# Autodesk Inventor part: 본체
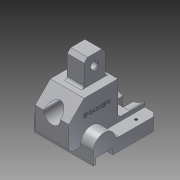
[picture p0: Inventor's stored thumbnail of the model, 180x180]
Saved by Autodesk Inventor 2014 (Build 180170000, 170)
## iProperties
Created: 2016-11
Part Number: 본체
Material: 알루미늄 6061
Document SubType Name: Modeling
Designer: USER
Density: 2.71 g/cm^3
Appearance: 알루미늄 - 평지
Mass: 462.907 g
Surface Area: 317.29 cm^2
Volume: 170.814 cm^3
Author: USER
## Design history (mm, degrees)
sketch "스케치1"
  geometry: L1 (0, 0)-(18, 18); L2 (18, 18)-(58, 18); L3 (58, 18)-(58, -22); L4 (58, -22)-(90, -22); L5 (90, -22)-(90, -42); L6 (90, -42)-(27, -42); L7 (27, -42)-(27, -30); L8 (27, -30)-(0, -30); L9 (0, -30)-(0, 0)
  constraints: 18 end point, 6 perpendicular, 1 horizontal, 1 parallel
  dimensions: "d0" = 45 deg angle of L1 L2; "d1" = 30 distance from line of L8 L1.start; "d2" = 58 distance between parallel lines of L3 L9; "d3" = 90 distance between parallel lines of L5 L9; "d4" = 48 distance between parallel lines of L8 L2; "d5" = 60 distance between parallel lines of L6 L2; "d6" = 20 distance of L4.end L5.end; "d7" = 63 distance of L5.end L6.end
extrude "돌출1" new body sketch "스케치1" stored distance "d8" = 40; taper "d9" = 0 deg
sketch "스케치2"
  geometry: L1 (30, 0)-(30, 27) reference; L2 (30, 27)-(42, 27) reference; L3 (42, 27)-(42, 90) reference; L4 (42, 90)-(22, 90) reference; L5 (-18, 58)-(-18, 18) reference; L6 (27, 14)-(42, 14); L7 (42, 14)-(42, 17); L8 (42, 17)-(35, 17); L9 (35, 17)-(35, 37); L10 (35, 37)-(42, 37); L11 (27, 40)-(27, 90); A1 r 13 centre (27, 27) between (27, 40) and (27, 14)
  constraints: 12 end point, 6 perpendicular, 2 point on circle, 2 point on line, 1 centre point, 1 tangent
  dimensions: "d11" = 15 distance from line of A1.centre L3; "d12" = 63 distance from line of L4 A1.centre; "d13" = 20 distance of L8.end L9.end; "d14" = 3 distance of L6.end L7.end; "d15" = 7 distance of L7.end L8.end; "d16" = 7 distance between parallel lines of L3 L9; "d17" = 13 radius of A1; "d18" = 50 distance of L11.start L11.end
extrude "돌출2" join sketch "스케치2" distance "d19" = 15; taper "d20" = 0 deg
sketch "스케치3"
  geometry: L1 (-30, 27)-(-35, 27) reference; L2 (-42, 17)-(-35, 17) reference; L3 (-30, 14)-(-42, 14) reference; L4 (-30, 14)-(-30, 27) reference; L5 (-35, 27)-(-30, 27); L6 (-30, 14)-(-42, 14); L7 (-35, 27)-(-35, 17); L8 (-35, 17)-(-42, 17); L9 (-42, 17)-(-42, 14); L10 (-30, 27)-(-30, 14); 1 further point
  constraints: 12 end point, 3 collinear, 3 perpendicular
extrude "돌출3" join sketch "스케치3" stored distance "d21" = 15; taper "d22" = 0 deg
sketch "스케치4"
  geometry: L1 (35, 17)-(42, 17); L2 (42, 17)-(42, 37); L3 (42, 37)-(35, 37); L4 (35, 37)-(35, 17); 1 further point
  constraints: 8 end point, 2 parallel, 1 horizontal, 1 perpendicular
extrude "돌출4" cut sketch "스케치4" stored distance "d23" = 0; taper "d24" = 0 deg
sketch "스케치5"
  geometry: L1 (58, 18)-(18, 18) reference; L2 (28, 18)-(28, 48); L3 (28, 48)-(53, 48); L4 (53, 48)-(53, 18); L5 (58, -22)-(58, 18) reference; L6 (37, -42)-(90, -42) reference; 1 further point
  constraints: 6 end point, 3 perpendicular, 2 point on line
  dimensions: "d25" = 5 distance between parallel lines of L5 L4; "d26" = 25 distance of L2.end L3.end; "d27" = 90 distance between parallel lines of L6 L3
extrude "돌출5" join sketch "스케치5" stored distance "d28" = 20; taper "d29" = 0 deg
sketch "스케치6"
  geometry: L1 (-48, 28)-(-18, 28) reference; L2 (42, 37)-(42, 90) reference; C1 r 4 at (-35, 40.5); 1 further point
  constraints: 1 centre point
  dimensions: "d30" = 8 diameter of C1; "d31" = 12.5 distance from line of L1 C1.centre; "d32" = 77 distance from line of L2 C1.centre
extrude "돌출6" cut sketch "스케치6" distance "d33" = 20; taper "d34" = 0 deg
sketch "스케치7"
  geometry: L1 (0, 0)-(40, 0) reference; L2 (55, 60)-(-15, 60) reference; C1 r 14.5 at (20, 18); 2 further points
  constraints: 1 centre point, 1 midpoint, 1 vertical alignment
  dimensions: "d35" = 29 diameter of C1; "d36" = 42 distance from line of L2 C1.centre
extrude "돌출7" cut sketch "스케치7" distance "d37" = 7; taper "d38" = 0 deg
sketch "스케치8"
  geometry: C1 r 14.5 at (0, 0) reference; C2 r 10 at (0, 0)
  constraints: 1 centre point, 1 coincident
  dimensions: "d39" = 20 diameter of C2
extrude "돌출8" cut sketch "스케치8" stored distance "d40" = 7; taper "d41" = 0 deg
chamfer "모따기1" distance "d42" = 1; stored, may be unused: second distance "d43" = 2, angle "d44" = 45 deg
sketch "스케치9"
  geometry: C1 r 29 at (20, -22); 1 further point
  constraints: 1 centre point, 1 coincident
  dimensions: "d45" = 58 diameter of C1
extrude "돌출9" cut sketch "스케치9" distance "d46" = 18; taper "d47" = 0 deg
sketch "스케치10"
  geometry: L1 (38.894, 14)-(1.106, 14) reference; L2 (14, 14)-(26, 14); L3 (26, 14)-(26, 45.797); L4 (26, 45.797)-(14, 45.797); L5 (14, 45.797)-(14, 14); 4 further points
  constraints: 8 end point, 3 midpoint, 2 coincident, 2 parallel, 1 horizontal, 1 perpendicular
  dimensions: "d48" = 31.79699 distance of L4.end L2.start; "d49" = 12 distance of L3.end L4.end
extrude "돌출10" cut sketch "스케치10" distance "d50" = 30; taper "d51" = 0 deg
sketch "스케치11"
  geometry: L1 (15, 0)-(0, 0) reference; L2 (45, -90)-(25, -90) reference; L3 (55, 0)-(70, 0) reference; L4 (53.894, -18)-(16.106, -18) reference; L5 (35, -18)-(35, 7.709); 3 further points
  constraints: 2 end point, 1 midpoint, 1 perpendicular
  dimensions: "d52" = 18 distance from line of L1 point (7.5, -18); "d53" = 18 distance from line of L3 point (62.5, -18); "d54" = 55 distance of point (62.5, -18) point (7.5, -18); "d55" = 27.5 distance from line of L5 point (7.5, -18)
hole "구멍1" sketch "스케치11" at (7.5, -18), (62.5, -18) diameter "d56" = 3.242; stored, may be unused: countersink angle "d60" = 90 deg, drill point angle "d62" = 118 deg; dims "d57" = 6, "d58" = 4, "d59" = 2, "d61" = 8
chamfer "모따기2" distance "d63" = 4; stored, may be unused: second distance "d64" = 2, angle "d65" = 45 deg
chamfer "모따기4" distance "d69" = 5; stored, may be unused: second distance "d70" = 2, angle "d71" = 45 deg
fillet "모깎기1" dims "d72" = 5
fillet "모깎기2" dims "d73" = 3
sketch "스케치12"
  geometry: L1 (19, 58)-(-18, 58) reference; L2 (-18, 58)-(-18, 18) reference; 1 further point
  constraints: 1 other
  dimensions: "d74" = 25 distance from line of L1 point (0, 33); "d75" = 18 distance from line of L2 point (0, 33)
feature "엠보싱1" sketch "스케치12" dims "d0" = 45 deg, "d1" = 30, "d2" = 58, "d3" = 90, "d4" = 48, "d5" = 60, "d6" = 20, "d7" = 63, "d11" = 15, "d12" = 63, "d13" = 20, "d14" = 3, "d15" = 7, "d16" = 7, "d17" = 13, "d18" = 50, "d76" = 0.5, "d77" = 0
chamfer "모따기5" distance "d78" = 4; stored, may be unused: second distance "d79" = 2, angle "d80" = 45 deg
chamfer "모따기6" distance "d81" = 1; stored, may be unused: second distance "d82" = 2, angle "d83" = 45 deg
node "솔리드1"
mirror "대칭1"
other parameters: "d10" = 26
